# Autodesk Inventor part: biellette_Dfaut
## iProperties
Created: 2006-03
Part Number: biellette_Dfaut
Document SubType Name: Modeling
Designer: Flavien MARTY
Author: Flavien MARTY
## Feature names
1. Base1
